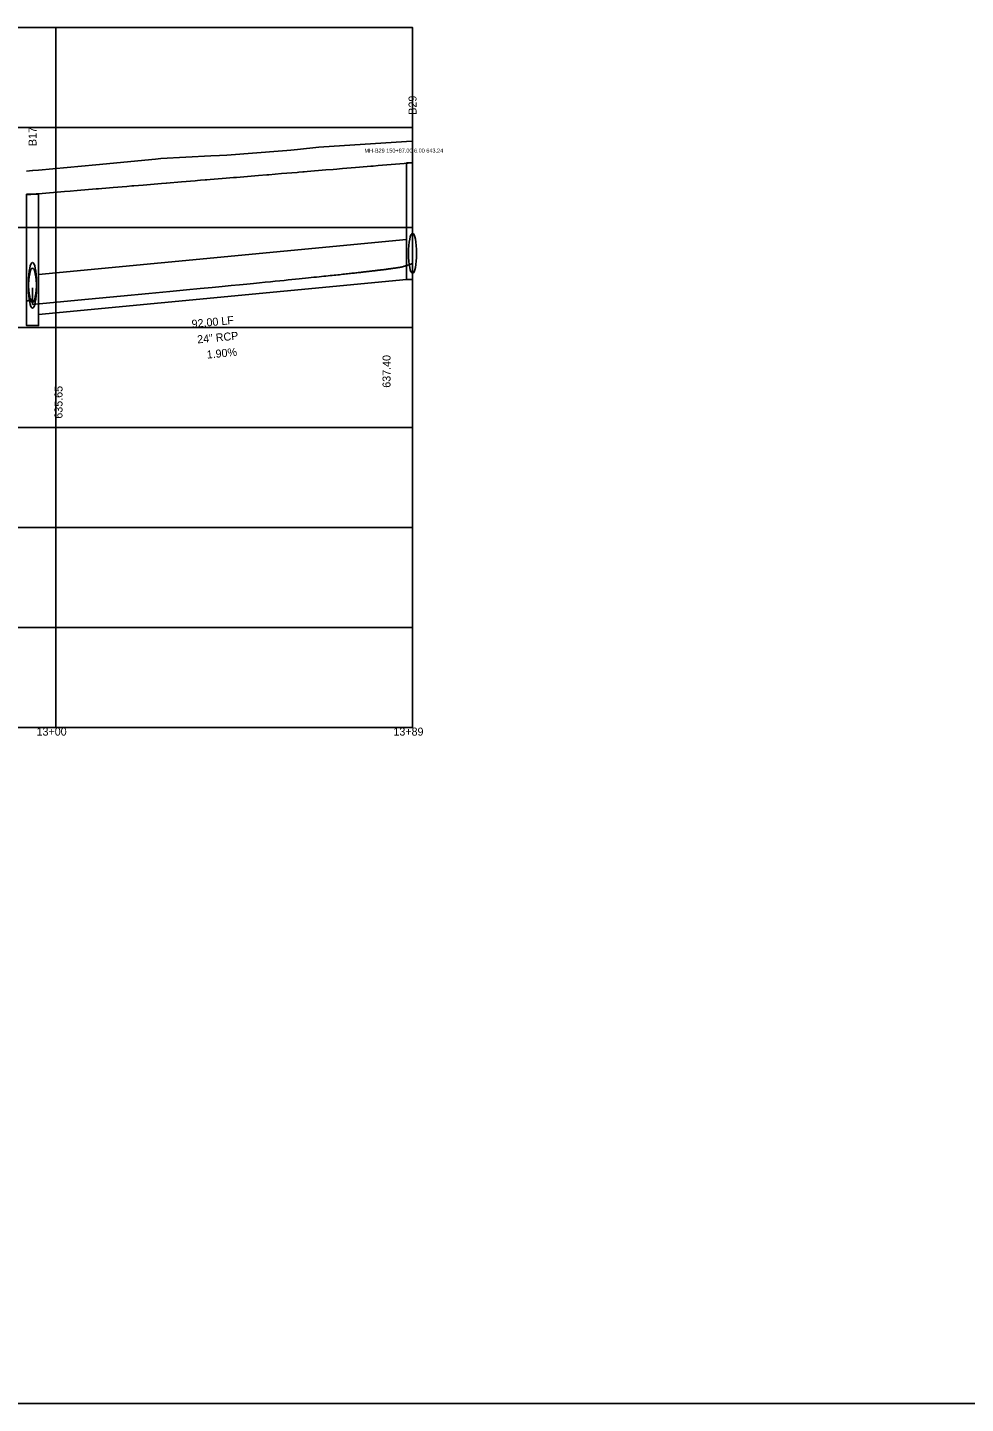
# Model space of a CAD drawing. Extents: x 2253035 to 2279930, y 13774972 to 13793443.
# Drawn here: x 2261254.4 to 2261488.9, y 13791972.5 to 13792316.4 of the extents above; entities that cross this region are included whole.
import ezdxf

# ---------------------------------------------------------------- set-up
doc = ezdxf.new("R2010")
doc.units = 0
for name, color, linetype in [('Default', 7, 'Continuous'), ('E_Utility_ATT_HH', 7, 'Continuous'), ('E_Utility_ATT_PR_PVC', 7, 'Continuous'), ('E_Utility_Telephone_Telephone Pedestal_TPED_Description', 7, 'Continuous'), ('E_Utillity_Water_Water Line_12in', 7, 'Continuous'), ('E_Utillity_Water_Water Line_1in', 7, 'Continuous'), ('E_Utillity_Water_Water Line_4in', 7, 'Continuous'), ('E_Utillity_Water_Water Line_8in', 7, 'Continuous')]:
    doc.layers.add(name, color=color, linetype=linetype)

msp = doc.modelspace()

# ---------------------------------------------------------------- linework, layer by layer
at = {"layer": 'Default'}
for p, q in [((2261261.48, 13792141.44), (2261261.48, 13792316.44)), ((2259961.48, 13792291.44), (2261350.66, 13792291.44)), ((2259961.48, 13792266.44), (2261350.66, 13792266.44)), ((2259961.48, 13792241.44), (2261350.66, 13792241.44)), ((2259961.48, 13792216.44), (2261350.66, 13792216.44)), ((2259961.48, 13792191.44), (2261350.66, 13792191.44)), ((2259961.48, 13792166.44), (2261350.66, 13792166.44)), ((2258357.4, 13791972.48), (2265626.63, 13791972.48))]:
    msp.add_line(p, q, dxfattribs=at)
msp.add_lwpolyline([(2259961.48, 13792141.44), (2259961.48, 13792316.44), (2261350.66, 13792316.44), (2261350.66, 13792141.44)], close=True, dxfattribs=at)
at = {"layer": 'E_Utility_ATT_PR_PVC'}
msp.add_line((2261255.66, 13792251.33), (2261255.66, 13792247.18), dxfattribs=at)
for points in [[(2261255.66, 13792247.18), (2261266.98, 13792248.26), (2261277.69, 13792249.28), (2261284.74, 13792249.96), (2261289.99, 13792250.46), (2261294.16, 13792250.86), (2261297.61, 13792251.19), (2261300.55, 13792251.48), (2261303.1, 13792251.73), (2261305.36, 13792251.94), (2261307.38, 13792252.14), (2261309.21, 13792252.32), (2261310.87, 13792252.48), (2261312.4, 13792252.63), (2261313.81, 13792252.77), (2261315.12, 13792252.9), (2261316.34, 13792253.02), (2261317.49, 13792253.14), (2261318.56, 13792253.24), (2261319.57, 13792253.34), (2261320.52, 13792253.44), (2261321.43, 13792253.53), (2261322.29, 13792253.62), (2261323.1, 13792253.7), (2261323.88, 13792253.78), (2261324.62, 13792253.85), (2261325.33, 13792253.93), (2261326.01, 13792254), (2261326.66, 13792254.06), (2261327.29, 13792254.13), (2261327.89, 13792254.19), (2261328.46, 13792254.25), (2261329.02, 13792254.31), (2261329.56, 13792254.36), (2261330.07, 13792254.42), (2261330.57, 13792254.47), (2261331.06, 13792254.52), (2261331.52, 13792254.57), (2261331.98, 13792254.62), (2261332.41, 13792254.66), (2261332.84, 13792254.71), (2261333.25, 13792254.75), (2261333.65, 13792254.8), (2261334.03, 13792254.84), (2261334.41, 13792254.88), (2261334.78, 13792254.92), (2261335.13, 13792254.96), (2261335.48, 13792255), (2261335.81, 13792255.03), (2261336.14, 13792255.07), (2261336.46, 13792255.1), (2261336.77, 13792255.14), (2261337.07, 13792255.17), (2261337.37, 13792255.21), (2261337.65, 13792255.24), (2261337.93, 13792255.27), (2261338.21, 13792255.3), (2261338.47, 13792255.33), (2261338.73, 13792255.36), (2261338.99, 13792255.39), (2261339.24, 13792255.42), (2261339.48, 13792255.45), (2261339.72, 13792255.47), (2261339.95, 13792255.5), (2261340.17, 13792255.53), (2261340.4, 13792255.55), (2261340.61, 13792255.58), (2261340.82, 13792255.6), (2261341.03, 13792255.63), (2261341.23, 13792255.65), (2261341.43, 13792255.68), (2261341.63, 13792255.7), (2261341.82, 13792255.72), (2261342, 13792255.75), (2261342.19, 13792255.77), (2261342.36, 13792255.79), (2261342.54, 13792255.81), (2261342.71, 13792255.83), (2261342.88, 13792255.85), (2261343.04, 13792255.87), (2261343.2, 13792255.89), (2261343.36, 13792255.91), (2261343.52, 13792255.93), (2261343.67, 13792255.95), (2261343.82, 13792255.97), (2261343.96, 13792255.99), (2261344.11, 13792256.01), (2261344.25, 13792256.03), (2261344.39, 13792256.05), (2261344.52, 13792256.06), (2261344.65, 13792256.08), (2261344.78, 13792256.1), (2261344.91, 13792256.12), (2261345.04, 13792256.13), (2261345.16, 13792256.15), (2261345.28, 13792256.17), (2261345.4, 13792256.18), (2261345.51, 13792256.2), (2261345.63, 13792256.22), (2261345.74, 13792256.23), (2261345.85, 13792256.25), (2261345.96, 13792256.26), (2261346.06, 13792256.28), (2261346.16, 13792256.29), (2261346.27, 13792256.31), (2261346.37, 13792256.32), (2261346.46, 13792256.33), (2261346.56, 13792256.35), (2261346.65, 13792256.36), (2261346.75, 13792256.38), (2261346.84, 13792256.39), (2261346.93, 13792256.4), (2261347.01, 13792256.42), (2261347.1, 13792256.43), (2261347.18, 13792256.44), (2261347.27, 13792256.46), (2261347.35, 13792256.47), (2261347.43, 13792256.48), (2261347.51, 13792256.49), (2261347.58, 13792256.51), (2261347.66, 13792256.52), (2261347.73, 13792256.54), (2261347.81, 13792256.56), (2261347.88, 13792256.57), (2261347.95, 13792256.59), (2261348.02, 13792256.61), (2261348.08, 13792256.63), (2261348.15, 13792256.65), (2261348.22, 13792256.66), (2261348.28, 13792256.68), (2261348.34, 13792256.7), (2261348.4, 13792256.71), (2261348.46, 13792256.73), (2261348.52, 13792256.75), (2261348.58, 13792256.76), (2261348.64, 13792256.78), (2261348.69, 13792256.79), (2261348.75, 13792256.81), (2261348.8, 13792256.82), (2261348.85, 13792256.84), (2261348.9, 13792256.85), (2261348.96, 13792256.87), (2261349, 13792256.88), (2261349.05, 13792256.9), (2261349.1, 13792256.91), (2261349.15, 13792256.93), (2261349.19, 13792256.94), (2261349.24, 13792256.95), (2261349.28, 13792256.97), (2261349.32, 13792256.98), (2261349.37, 13792256.99), (2261349.41, 13792257), (2261349.45, 13792257.02), (2261349.49, 13792257.03), (2261349.53, 13792257.04), (2261349.56, 13792257.05), (2261349.6, 13792257.07), (2261349.64, 13792257.08), (2261349.67, 13792257.09), (2261349.71, 13792257.1), (2261349.74, 13792257.11), (2261349.77, 13792257.12), (2261349.81, 13792257.14), (2261349.84, 13792257.15), (2261349.87, 13792257.16), (2261349.9, 13792257.17), (2261349.93, 13792257.18), (2261349.96, 13792257.19), (2261349.99, 13792257.2), (2261350.01, 13792257.21), (2261350.04, 13792257.22), (2261350.07, 13792257.23), (2261350.09, 13792257.24), (2261350.12, 13792257.25), (2261350.14, 13792257.26), (2261350.16, 13792257.27), (2261350.19, 13792257.28), (2261350.21, 13792257.29), (2261350.23, 13792257.3), (2261350.25, 13792257.3), (2261350.27, 13792257.31), (2261350.29, 13792257.32), (2261350.31, 13792257.33), (2261350.33, 13792257.34), (2261350.35, 13792257.35), (2261350.36, 13792257.36), (2261350.38, 13792257.36), (2261350.4, 13792257.37), (2261350.41, 13792257.38), (2261350.43, 13792257.39), (2261350.44, 13792257.4), (2261350.46, 13792257.4), (2261350.47, 13792257.41), (2261350.48, 13792257.42), (2261350.5, 13792257.43), (2261350.51, 13792257.43), (2261350.52, 13792257.44), (2261350.53, 13792257.45), (2261350.54, 13792257.46), (2261350.55, 13792257.46), (2261350.56, 13792257.47), (2261350.57, 13792257.48), (2261350.58, 13792257.48), (2261350.59, 13792257.49), (2261350.6, 13792257.5), (2261350.6, 13792257.5), (2261350.61, 13792257.51), (2261350.62, 13792257.51), (2261350.62, 13792257.52), (2261350.63, 13792257.53), (2261350.63, 13792257.53), (2261350.64, 13792257.54), (2261350.64, 13792257.54), (2261350.65, 13792257.55), (2261350.65, 13792257.56), (2261350.65, 13792257.56), (2261350.66, 13792257.57), (2261350.66, 13792257.57), (2261350.66, 13792257.58), (2261350.66, 13792257.58), (2261350.66, 13792257.59), (2261350.66, 13792257.59), (2261350.66, 13792257.6), (2261350.66, 13792257.6), (2261350.66, 13792258.64)], [(2261254.41, 13792248.09), (2261254.44, 13792248.1), (2261254.47, 13792248.11), (2261254.5, 13792248.12), (2261254.53, 13792248.13), (2261254.56, 13792248.14), (2261254.59, 13792248.15), (2261254.62, 13792248.16), (2261254.64, 13792248.17), (2261254.67, 13792248.18), (2261254.7, 13792248.19), (2261254.72, 13792248.2), (2261254.75, 13792248.21), (2261254.77, 13792248.22), (2261254.8, 13792248.23), (2261254.82, 13792248.24), (2261254.85, 13792248.25), (2261254.87, 13792248.26), (2261254.89, 13792248.27), (2261254.92, 13792248.28), (2261254.94, 13792248.28), (2261254.96, 13792248.29), (2261254.98, 13792248.3), (2261255, 13792248.31), (2261255.02, 13792248.32), (2261255.04, 13792248.33), (2261255.06, 13792248.34), (2261255.08, 13792248.35), (2261255.1, 13792248.35), (2261255.12, 13792248.36), (2261255.14, 13792248.37), (2261255.16, 13792248.38), (2261255.18, 13792248.39), (2261255.19, 13792248.4), (2261255.21, 13792248.4), (2261255.23, 13792248.41), (2261255.24, 13792248.42), (2261255.26, 13792248.43), (2261255.28, 13792248.44), (2261255.29, 13792248.44), (2261255.31, 13792248.45), (2261255.32, 13792248.46), (2261255.34, 13792248.47), (2261255.35, 13792248.47), (2261255.36, 13792248.48), (2261255.38, 13792248.49), (2261255.39, 13792248.5), (2261255.4, 13792248.5), (2261255.41, 13792248.51), (2261255.43, 13792248.52), (2261255.44, 13792248.52), (2261255.45, 13792248.53), (2261255.46, 13792248.54), (2261255.47, 13792248.55), (2261255.48, 13792248.55), (2261255.49, 13792248.56), (2261255.5, 13792248.57), (2261255.51, 13792248.57), (2261255.52, 13792248.58), (2261255.53, 13792248.59), (2261255.54, 13792248.59), (2261255.55, 13792248.6), (2261255.55, 13792248.61), (2261255.56, 13792248.61), (2261255.57, 13792248.62), (2261255.58, 13792248.62), (2261255.58, 13792248.63), (2261255.59, 13792248.64), (2261255.6, 13792248.64), (2261255.6, 13792248.65), (2261255.61, 13792248.65), (2261255.61, 13792248.66), (2261255.62, 13792248.67), (2261255.62, 13792248.67), (2261255.63, 13792248.68), (2261255.63, 13792248.68), (2261255.64, 13792248.69), (2261255.64, 13792248.7), (2261255.64, 13792248.7), (2261255.65, 13792248.71), (2261255.65, 13792248.71), (2261255.65, 13792248.72), (2261255.65, 13792248.72), (2261255.66, 13792248.73), (2261255.66, 13792248.73), (2261255.66, 13792248.74), (2261255.66, 13792248.74), (2261255.66, 13792248.75), (2261255.66, 13792248.75), (2261255.66, 13792248.76), (2261255.66, 13792248.76), (2261255.66, 13792248.77), (2261255.66, 13792251.33)]]:
    msp.add_lwpolyline(points, dxfattribs=at)
at = {"layer": 'E_Utillity_Water_Water Line_12in'}
for points in [[(2261349.16, 13792282.62), (2261350.66, 13792282.62), (2261350.66, 13792253.44), (2261349.16, 13792253.44)], [(2261254.16, 13792274.78), (2261257.16, 13792274.78), (2261257.16, 13792241.94), (2261254.16, 13792241.94)]]:
    msp.add_lwpolyline(points, close=True, dxfattribs=at)
at = {"layer": 'E_Utillity_Water_Water Line_1in'}
msp.add_lwpolyline([(2261254.16, 13792280.53), (2261255.66, 13792280.67), (2261255.66, 13792280.67), (2261257.16, 13792280.81), (2261257.16, 13792280.81), (2261271.5, 13792282.14), (2261286.38, 13792283.54), (2261287.7, 13792283.69), (2261300.24, 13792284.33), (2261302.44, 13792284.48), (2261304.24, 13792284.54), (2261318.15, 13792285.64), (2261319.22, 13792285.71), (2261320.26, 13792285.82), (2261321.92, 13792285.97), (2261327.27, 13792286.52), (2261349.16, 13792287.96), (2261349.16, 13792287.96), (2261350.66, 13792288.05)], dxfattribs=at)
at = {"layer": 'E_Utillity_Water_Water Line_4in'}
for p, q in [((2261257.16, 13792254.7), (2261349.16, 13792263.44)), ((2261257.16, 13792244.7), (2261349.16, 13792253.44))]:
    msp.add_line(p, q, dxfattribs=at)
for centre in [(2261350.66, 13792259.98), (2261255.66, 13792252.71), (2261255.66, 13792251.31)]:
    msp.add_ellipse(centre, major_axis=(0, 5), ratio=0.2, dxfattribs=at)
at = {"layer": 'E_Utillity_Water_Water Line_8in'}
msp.add_lwpolyline([(2261254.28, 13792274.67), (2261255.14, 13792274.74), (2261255.29, 13792274.75), (2261255.66, 13792274.78), (2261255.66, 13792274.78), (2261256.56, 13792274.86), (2261257.16, 13792274.91), (2261257.16, 13792274.91), (2261263.62, 13792275.44), (2261263.65, 13792275.44), (2261263.68, 13792275.44), (2261265.07, 13792275.56), (2261266.79, 13792275.7), (2261271.58, 13792276.09), (2261272.16, 13792276.14), (2261273.03, 13792276.21), (2261273.96, 13792276.29), (2261275.8, 13792276.44), (2261279.23, 13792276.73), (2261280.47, 13792276.83), (2261280.67, 13792276.84), (2261280.95, 13792276.87), (2261283.31, 13792277.06), (2261287.92, 13792277.44), (2261289.04, 13792277.54), (2261289.17, 13792277.55), (2261289.18, 13792277.55), (2261292.87, 13792277.85), (2261296.28, 13792278.13), (2261296.93, 13792278.19), (2261297.69, 13792278.25), (2261298.86, 13792278.35), (2261299.26, 13792278.38), (2261300.05, 13792278.44), (2261304.07, 13792278.78), (2261305.89, 13792278.93), (2261306.2, 13792278.95), (2261306.66, 13792278.99), (2261308.51, 13792279.14), (2261312.17, 13792279.44), (2261314.24, 13792279.61), (2261314.66, 13792279.65), (2261314.71, 13792279.65), (2261317.92, 13792279.92), (2261321.81, 13792280.24), (2261322.26, 13792280.28), (2261323.23, 13792280.36), (2261323.55, 13792280.38), (2261324.29, 13792280.44), (2261329.01, 13792280.83), (2261330.79, 13792280.98), (2261331.74, 13792281.06), (2261332.4, 13792281.11), (2261333.15, 13792281.17), (2261336.41, 13792281.44), (2261339.28, 13792281.68), (2261340.25, 13792281.76), (2261340.8, 13792281.81), (2261342.08, 13792281.91), (2261344.24, 13792282.09), (2261348.53, 13792282.44), (2261349.16, 13792282.5), (2261349.16, 13792282.5), (2261349.53, 13792282.53), (2261349.57, 13792282.53), (2261349.58, 13792282.53), (2261350.66, 13792282.62)], dxfattribs=at)

# ---------------------------------------------------------------- texts
at = {"layer": 'Default'}
for s, p in [('13+00', (2261256.68, 13792139.44)), ('13+89', (2261345.88, 13792139.44))]:
    msp.add_text(s, height=2, dxfattribs=at).set_placement(p)
at = {"layer": 'E_Utility_ATT_HH'}
for s, rotation, p in [('B29', 90, (2261351.66, 13792294.64)), ('B17', 90, (2261256.66, 13792286.81)), ('92.00 LF', 5.4268, (2261295.54, 13792241.35)), ('24" RCP', 5.4268, (2261296.92, 13792237.47)), ('1.90%', 5.4268, (2261299.3, 13792233.67)), ('637.40', 90, (2261345.16, 13792226.4)), ('635.65', 90, (2261263.16, 13792218.67))]:
    msp.add_text(s, height=2, rotation=rotation, dxfattribs=at).set_placement(p)
at = {"layer": 'E_Utility_Telephone_Telephone Pedestal_TPED_Description'}
msp.add_text('MH-B29 150+87.00 6.00 643.24', height=1, rotation=0, dxfattribs=at).set_placement((2261338.63, 13792285.17))

doc.saveas('drawing.dxf')
